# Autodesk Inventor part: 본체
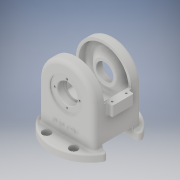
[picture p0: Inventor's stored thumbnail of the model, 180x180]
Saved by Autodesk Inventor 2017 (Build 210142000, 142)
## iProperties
Part Number: 본체
Material: 일반
Document SubType Name: Modeling
Designer: MRC
Density: 1 g/cm^3
Appearance: 기본값
Author: MRC
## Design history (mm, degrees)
sketch "스케치1"
  geometry: C1 r 71 at (0, 0); 1 further point
  constraints: 1 centre point, 1 coincident
  dimensions: "d0" = 142 diameter of C1
extrude "돌출1" new body sketch "스케치1" distance "d1" = 13; taper "d2" = 0 deg
sketch "스케치2"
  geometry: C1 r 51 at (0, 81); 1 further point
  constraints: 1 centre point, 1 vertical alignment
  dimensions: "d3" = 102 diameter of C1; "d4" = 81 distance of point (0, 0) C1.centre
extrude "돌출2" join sketch "스케치2" stored distance "d5" = 88; taper "d6" = 0 deg
sketch "스케치3"
  geometry: L1 (51, 81)-(51, 13); L2 (71, 13)-(-71, 13) reference; L3 (-51, 13)-(-51, 81); L4 (51, 81)-(-51, 81); L5 (-51, 13)-(51, 13); A1 r 51 centre (0, 81) between (-51, 81) and (51, 81) reference; 1 further point
  constraints: 8 end point, 2 point on circle, 1 collinear, 1 parallel, 1 perpendicular, 1 point on line, 1 tangent, 1 vertical
extrude "돌출3" join sketch "스케치3" stored distance "d10" = 88; taper "d11" = 0 deg
sketch "스케치5"
  geometry: L1 (-24, 68)-(-64, 68); L2 (-64, 68)-(-64, 48); L3 (-64, 48)-(-24, 48); L4 (-24, 48)-(-24, 68); L5 (-24, 68)-(-64, 48); L6 (-64, 68)-(-24, 48); L7 (-115, -13)-(27, -13) reference; 4 further points
  constraints: 12 end point, 4 midpoint, 2 parallel, 1 horizontal, 1 perpendicular, 1 vertical alignment
  dimensions: "d12" = 40 distance of L3.end L2.end; "d13" = 20 distance of L2.end L1.end; "d43" = 81 distance between parallel lines of L1 L7
extrude "돌출4" join sketch "스케치5" distance "d15" = 10; taper "d16" = 0 deg
sketch "스케치6"
  geometry: L1 (-71, 0)-(71, 0) reference; C1 r 30 at (0, 81); 1 further point
  constraints: 1 centre point, 1 vertical alignment
  dimensions: "d17" = 60 diameter of C1; "d18" = 81 distance from line of L1 C1.centre
extrude "돌출5" cut sketch "스케치6" distance "d19" = 2; taper "d20" = 0 deg
sketch "스케치7"
  geometry: L1 (-71, -81)-(71, -81) reference; C1 r 18.5 at (0, 0); 2 further points
  constraints: 1 centre point, 1 midpoint, 1 vertical alignment
  dimensions: "d21" = 37 diameter of C1; "d22" = 81 distance from line of L1 C1.centre
extrude "돌출6" cut sketch "스케치7" distance "d23" = 13; taper "d24" = 0 deg
sketch "스케치8"
  geometry: C1 r 16 at (0, 0); 1 further point
  constraints: 1 centre point, 1 vertical alignment
  dimensions: "d25" = 32 diameter of C1; "d26" = 81 distance of point (0, -81) C1.centre
extrude "돌출7" cut sketch "스케치8" distance "d27" = 2; taper "d28" = 0 deg
sketch "스케치9"
  geometry: C1 r 16 at (0, 0) reference; C2 r 16 at (0, 0); 1 further point
  constraints: 1 centre point, 1 coincident
  dimensions: "d29" = 32 diameter of C2
extrude "돌출8" cut sketch "스케치9" stored distance "d30" = 2; taper "d31" = 0 deg
sketch "스케치10"
  geometry: L1 (19, -28)-(0, -28); L2 (0, -28)-(0, 28); L3 (0, 28)-(19, 28); L4 (19, 28)-(19, -28); L5 (0, 71)-(0, -71) reference; 2 further points
  constraints: 8 end point, 2 midpoint, 2 parallel, 1 coincident, 1 collinear, 1 horizontal, 1 perpendicular
  dimensions: "d34" = 19 distance of L2.end L3.end; "d35" = 56 distance of L1.end L2.end
extrude "돌출9" cut sketch "스케치10" stored distance "d36" = 2; taper "d37" = 0 deg
extrude "돌출10" cut sketch "스케치10" stored distance "d38" = 2; taper "d39" = 0 deg
sketch "스케치11"
  geometry: L1 (-16, 6)-(-72, 6) reference; L2 (-115, -13)-(-72, -13) reference; L3 (-16, -13)-(27, -13) reference; L4 (-19, 119)-(-69, 119); L5 (-69, 119)-(-69, 68); L6 (-69, 68)-(-19, 68); L7 (-19, 68)-(-19, 119); L8 (-19, 119)-(-69, 68); L9 (-69, 119)-(-19, 68); 3 further points
  constraints: 12 end point, 3 midpoint, 2 parallel, 1 horizontal, 1 perpendicular, 1 vertical alignment
  dimensions: "d40" = 50 distance of L6.end L5.end; "d41" = 51 distance of L5.end L4.end; "d44" = 81 distance from line of L6.end L3
extrude "돌출11" cut sketch "스케치11" stored distance "d45" = 2; taper "d46" = 0 deg
sketch "스케치12"
  geometry: L1 (-51, 13)-(-51, 81) reference; L2 (51, 81)-(51, 13) reference; L3 (-46, 40)-(-46, 81); L4 (46, 81)-(46, 40); L5 (-46, 40)-(46, 40); L6 (65.246, 0)-(-65.246, 0) reference; A1 r 51 centre (0, 81) between (51, 81) and (-51, 81) reference; A2 r 46 centre (0, 81) between (46, 81) and (-46, 81); 1 further point
  constraints: 6 end point, 2 point on circle, 1 centre point, 1 perpendicular
  dimensions: "d47" = 5 radial gap between concentric circles of A1 A2; "d48" = 40 distance between parallel lines of L5 L6; "d49" = 5 distance between parallel lines of L1 L3; "d50" = 5 distance between parallel lines of L2 L4
extrude "돌출12" cut sketch "스케치12" stored distance "d51" = 78; taper "d52" = 0 deg
sketch "스케치13"
  geometry: L1 (81, 25)-(81, -25) reference; L2 (127, 25)-(127, 39) reference; L3 (102.5, 27)-(114.5, 39); L4 (81, 20)-(81, 25) reference; L5 (81, 39)-(40, 39) reference; L6 (62.5, 42)-(99.5, 42) reference; L7 (127, 39)-(81, 39) reference; L8 (114.5, 39)-(81, 39); L9 (81, 39)-(81, 27); L10 (81, 25)-(81, 44) reference; L11 (102.5, 27)-(81, 27); 1 further point
  constraints: 8 end point, 1 horizontal, 1 perpendicular, 1 point on line
  dimensions: "d53" = 12 distance between parallel lines of L11 L7; "d54" = 45 deg angle of L2 L3; "d55" = 33.5 distance from line of L9 L3.end
revolve "회전1" sketch "스케치13" stored, may be unused: angle "d56" = 90 deg
sketch "스케치14"
  geometry: C1 r 21.5 at (0, 0) reference; C2 r 16 at (0, 0); 1 further point
  constraints: 1 centre point, 1 coincident
  dimensions: "d57" = 32 diameter of C2
extrude "돌출13" cut sketch "스케치14" stored distance "d58" = 10; taper "d59" = 0 deg
sketch "스케치15"
  geometry: C1 r 18.5 at (0, 0) reference; 1 further point
extrude "돌출14" cut sketch "스케치15" distance "d60" = 13; taper "d61" = 0 deg
sketch "스케치16" dims "d62" = 46
  geometry: C1 r 18.5 at (0, 0) reference; C2 r 30 at (0, 0) reference; 3 further points
  constraints: 2 vertical alignment, 1 coincident, 2 other
hole "구멍1" sketch "스케치16" at (0, 23) diameter "d63" = 3.242; stored, may be unused: countersink angle "d67" = 90 deg, drill point angle "d69" = 118 deg; dims "d64" = 8, "d65" = 4, "d66" = 2, "d68" = 10
sketch "스케치17"
  geometry: L1 (-105, 7)-(3, 7); L2 (3, 7)-(3, 33); L3 (3, 33)-(-105, 33); L4 (-105, 33)-(-105, 7); L5 (-105, 7)-(3, 33); L6 (3, 7)-(-105, 33); 5 further points
  constraints: 12 end point, 4 coincident, 2 midpoint, 2 parallel, 1 horizontal, 1 perpendicular
  dimensions: "d74" = 26 distance of L1.end L2.end; "d75" = 108 distance of L1.start L1.end
hole "구멍2" sketch "스케치17" at (-105, 7), (-105, 33), (3, 7), (3, 33) diameter "d76" = 3.242; stored, may be unused: countersink angle "d80" = 90 deg, drill point angle "d82" = 118 deg; dims "d77" = 8, "d78" = 4, "d79" = 2, "d81" = 10
sketch "스케치19"
  geometry: L1 (-25, -55)-(25, -55); L2 (25, -55)-(25, 55); L3 (25, 55)-(-25, 55); L4 (-25, 55)-(-25, -55); L5 (-25, -55)-(25, 55); L6 (25, -55)-(-25, 55); 8 further points
  constraints: 12 end point, 6 coincident, 4 midpoint, 1 horizontal, 1 parallel, 1 perpendicular
  dimensions: "d83" = 50 distance of L3.end L2.end; "d84" = 110 distance of L2.end L1.end
hole "구멍3" sketch "스케치19" at (-25, -55), (25, -55), (25, 55), (-25, 55) diameter "d85" = 9; stored, may be unused: countersink angle "d89" = 90 deg, drill point angle "d91" = 0 deg; dims "d86" = 8, "d87" = 15, "d88" = 8.8, "d90" = 14
sketch "스케치20"
  geometry: C1 r 11 at (46, -39); 1 further point
  constraints: 1 centre point, 1 coincident
  dimensions: "d92" = 22 diameter of C1
extrude "돌출15" cut sketch "스케치20" stored distance "d93" = 13; taper "d94" = 0 deg
sketch "스케치21"
  geometry: C1 r 30 at (0, 0); 1 further point
  constraints: 1 centre point, 1 coincident
  dimensions: "d95" = 60 diameter of C1
extrude "돌출16" cut sketch "스케치21" distance "d96" = 22; taper "d97" = 0 deg
sketch "스케치22"
  geometry: C1 r 14 at (0, 0); 1 further point
  constraints: 1 centre point, 1 coincident
  dimensions: "d98" = 28 diameter of C1
extrude "돌출17" cut sketch "스케치22" distance "d99" = 15; taper "d100" = 0 deg
sketch "스케치23" dims "d101" = 46
  geometry: 3 further points
  constraints: 2 horizontal alignment, 1 coincident, 2 other
hole "구멍4" sketch "스케치23" at (23, 0) diameter "d102" = 3.242; stored, may be unused: countersink angle "d106" = 90 deg, drill point angle "d108" = 0 deg; dims "d103" = 8, "d104" = 15, "d105" = 8.8, "d107" = 10
sketch "스케치24"
  geometry: L1 (-65.246, 0)-(65.246, 0) reference; 3 further points
  constraints: 1 midpoint, 1 vertical alignment, 1 other
  dimensions: "d112" = 30 distance from line of L1 point (0, 30)
feature "엠보싱1" sketch "스케치24" dims "d113" = 0.5, "d114" = 0
fillet "모깎기1" dims "d115" = 8
fillet "모깎기2" dims "d116" = 3
fillet "모깎기3" dims "d117" = 3
fillet "모깎기4" dims "d118" = 3
fillet "모깎기5" dims "d119" = 3
fillet "모깎기6" dims "d120" = 3
chamfer "모따기1" distance "d121" = 1; stored, may be unused: second distance "d122" = 2, angle "d123" = 45 deg
fillet "모깎기7" dims "d124" = 0.3
fillet "모깎기8" dims "d125" = 6
node "솔리드1"
mirror "미러1"
mirror "미러2"
pattern_circular "원형 패턴1" dims angle "d71" = 360 deg
mirror "미러3"
pattern_circular "원형 패턴2" dims angle "d110" = 360 deg
node "투영된 루프1"
node "투영된 루프2"
node "투영된 루프3"
